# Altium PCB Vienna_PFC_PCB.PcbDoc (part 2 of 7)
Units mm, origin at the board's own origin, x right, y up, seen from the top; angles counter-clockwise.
Board outline 447.04 x 302.51 mm, 6 copper layers (Top Layer, Signal Layer 1, Signal Layer 2, Signal Layer 3, Signal Layer 4, Bottom Layer), stack 1.231 mm thick; 630 components, 255 nets, 1656 pads, 941 vias.
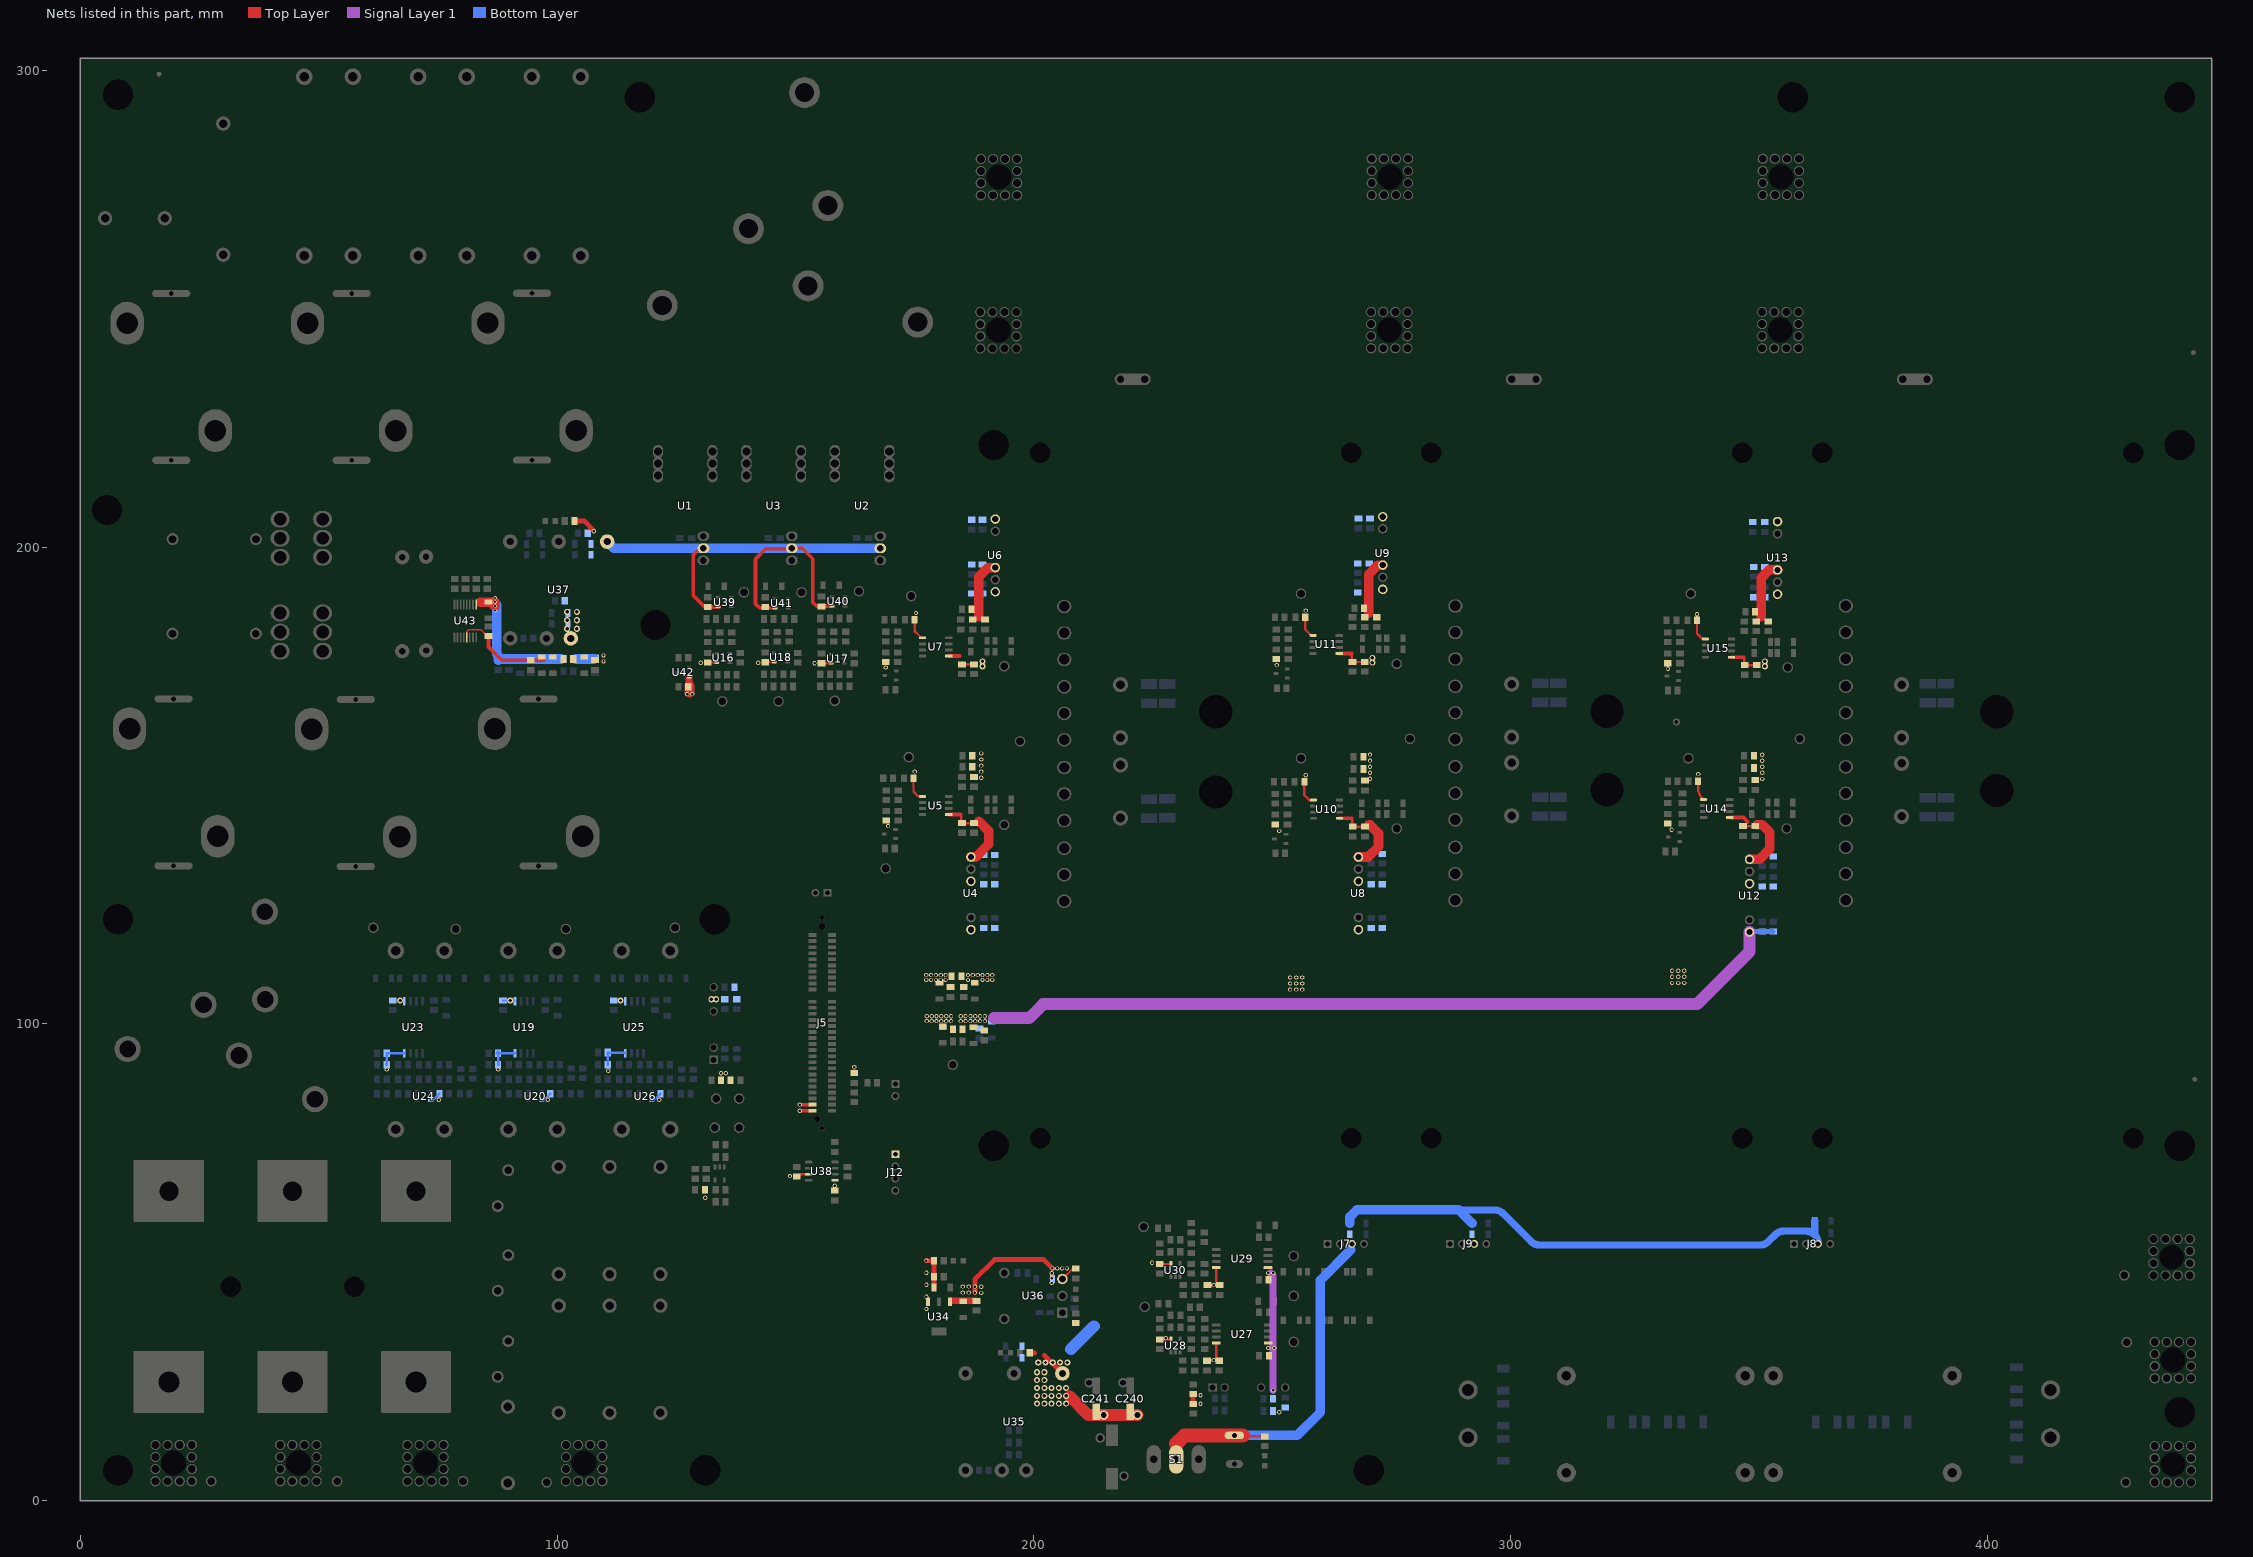
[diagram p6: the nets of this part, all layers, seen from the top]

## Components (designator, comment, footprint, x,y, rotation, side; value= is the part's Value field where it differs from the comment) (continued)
TP_VLI2 "5010" Keystone5010 78.74,119.888 r90 top
TP_VLI3 "5127" Keystone5127 124.714,120.142 r90 top value=Blue
TP_VLM "5012" Keystone5012 61.468,120.142 r90 top
TP_VNM "5011" Keystone5011 254.508,51.308 r90 top
TP_VPM "5010" Keystone5010 254.508,33.274 r90 top
TVS1 "B72214S2271K101" B72214S2271K101 88.646,65.532 r90 top
TVS2 "B72214S2271K101" B72214S2271K101 88.646,47.752 r90 top
TVS3 "B72214S2271K101" B72214S2271K101 88.646,29.718 r90 top
U1 "LAH 100-P" "LAH 100-P" 121.158,220.066 r270 top
U2 "LAH 100-P" "LAH 100-P" 158.242,220.066 r270 top
U3 "LAH 100-P" "LAH 100-P" 139.7,220.066 r270 top
U4 "R12P22005D" R12P22005D 189.484,127.254 r90 top
U5 "UCC5390S" UCC5390S 179.324,145.923 r0 top
U6 "R12P22005D" R12P22005D 189.23,198.374 r270 top
U7 "UCC5390S" UCC5390S 179.324,179.197 r0 top
U8 "R12P22005D" R12P22005D 270.764,127.254 r90 top
U9 "R12P22005D" R12P22005D 270.51,198.882 r270 top
U10 "UCC5390S" UCC5390S 261.317,145.161 r0 top
U11 "UCC5390S" UCC5390S 261.239,179.705 r0 top
U12 "R12P22005D" R12P22005D 352.806,126.746 r90 top
U13 "R12P22005D" R12P22005D 353.314,197.866 r270 top
U14 "UCC5390S" UCC5390S 343.154,145.288 r0 top
U15 "UCC5390S" UCC5390S 343.524,178.943 r0 top
U16 "MCP6021T-E/OT" OPA320 134.874,176.784 r180 top
U17 "MCP6021T-E/OT" OPA320 158.855,176.591 r180 top
U18 "MCP6021T-E/OT" OPA320 146.939,176.862 r180 top
U19 "AMC1301DWVR" AMC1301 93.091,99.314 r270 bottom
U20 "MCP6021T-E/OT" OPA320 95.377,84.836 r0 bottom
U21 "REF2033" REF2033 135.052,69.952 r180 top
U22 "DCH010505SN7" DCH010505SN7 132.842,100.076 r90 top
U23 "AMC1301DWVR" AMC1301 69.85,99.314 r270 bottom
U24 "MCP6021T-E/OT" OPA320 72.009,84.836 r0 bottom
U25 "AMC1301DWVR" AMC1301 116.205,99.314 r270 bottom
U26 "MCP6021T-E/OT" OPA320 118.491,84.836 r0 bottom
U27 "AMC1301DWVR" AMC1301 243.688,34.927 r180 top
U28 "MCP6021T-E/OT" OPA320 229.718,32.514 r90 top
U29 "AMC1301DWVR" AMC1301 243.662,50.775 r180 top
U30 "MCP6021T-E/OT" OPA320 229.692,48.362 r90 top
U31 "DCH010505SN7" DCH010505SN7 245.11,23.718 r0 top
U34 "MIC39100-3.3WS-TR" TLV1117 180.086,38.608 r270 top
U35 "S24SE12002PDFA" S24SE12002NDFA 198.374,6.35 r90 top
U36 "PTH08080WAH" PTH08080WAH 199.898,42.926 r180 top
U37 "S24DE150R3PDFA" S24SE12002NDFA 102.87,180.848 r90 top
U38 "ATA6561-GAQW-N" SOIC8 152.781,70.993 r0 top value=Value
U39 "MCP6V51T-E/OTCT-ND" OPA192 135.128,188.468 r180 top
U40 "MCP6V51T-E/OTCT-ND" OPA192 159.004,188.595 r180 top
U41 "MCP6V51T-E/OTCT-ND" OPA192 147.088,188.214 r180 top
U42 "REF3033AIDBZR" SOT-23 126.492,173.736 r180 top
U43 "TC78H611FNG" "TSSOP16_small pins" 80.731,184.51 r90 top
W1 "36-3065-ND" "WASHER SHOULDER" 191.581,74.415 r0 top
W2 "36-3065-ND" "WASHER SHOULDER" 7.874,6.35 r0 top
W3 "36-3065-ND" "WASHER SHOULDER" 440.341,18.542 r0 top
W4 "36-3065-ND" "WASHER SHOULDER" 440.341,74.415 r0 top
W5 "36-3065-ND" "WASHER SHOULDER" 191.581,221.415 r0 top locked
W6 "36-3065-ND" "WASHER SHOULDER" 117.348,294.386 r0 top
W7 "36-3065-ND" "WASHER SHOULDER" 133.064,121.92 r0 top
W8 "36-3065-ND" "WASHER SHOULDER" 440.341,221.415 r0 top
W9 "36-3065-ND" "WASHER SHOULDER" 7.874,121.92 r0 top
W10 "36-3065-ND" "WASHER SHOULDER" 5.588,207.772 r0 top
W11 "36-3065-ND" "WASHER SHOULDER" 120.65,183.642 r0 top
W12 "36-3065-ND" "WASHER SHOULDER" 131.064,6.35 r0 top
W13 "36-3065-ND" "WASHER SHOULDER" 7.874,294.894 r0 top
W14 "36-3065-ND" "WASHER SHOULDER" 270.256,6.35 r0 top
W15 "36-3065-ND" "WASHER SHOULDER" 359.156,294.386 r0 top
W16 "36-3065-ND" "WASHER SHOULDER" 440.341,294.386 r0 top
XF1 "Fuse Set" FuseHolde_Set 44.45,44.892 r90 top
XF2 "CG2470L" CG2470L 89.662,11.684 r270 top

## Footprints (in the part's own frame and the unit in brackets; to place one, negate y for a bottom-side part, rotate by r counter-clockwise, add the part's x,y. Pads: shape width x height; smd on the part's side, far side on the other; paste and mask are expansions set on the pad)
0805_HV [mil] "0805 with 30mil clearance between pads"
  rect 50x63 smd: 1(-40,0) 2(40,0)
  silkscreen extent -74,-40 74,40, body extent -43,-29 43,29, height 57
1206_190 [mm] "1206_190"
  rect 1.1x1.6 smd: 1(-1.7,0) 2(1.7,0)
  silkscreen extent -0.9,-1 0.9,1, body extent -1.75,-0.95 1.75,0.95, height 1.9
1812 [mm] "SMD, 2-Leads, Body 4.8x3.4mm"
  rect 2x3.4 smd: 1(-2,0) 2(2,0)
  silkscreen extent -0.8,-1.7 0.8,1.7, body extent -2.4,-1.7 2.4,1.7, height 2.54
2010 [mm] "Chip Capacitor, Body 5.08x2.54mm, IPC Medium Density"
  rect 1.6x2.7 smd: 1(-2.3,0) 2(2.3,0)
  silkscreen extent -3.42,-1.65 3.42,1.65, body extent -2.73,-1.45 2.73,1.45, height 1.66
AGP4233-332ME [mm] "Inductor"
  oval 1.5x8 hole 1 square: 0(-17.5,0) 0(17.5,0)
  oval 9x7 hole 4.5 square: 1(-11.274,-9.25) 2(11.274,9.25)
  silkscreen extent -22,-18.8 22,18.8, body extent -21.6,-18.4 21.6,18.4, height 31.3
AMC1301 [mm] "SOIC, 8-Leads, Body 5.95x7.6mm (max), Pitch 1.27mm"
  rrect17% 1.8x0.6 smd: 1(-5.45,1.905) 2(-5.45,0.635) 3(-5.45,-0.635) 4(-5.45,-1.905) 5(5.45,-1.905) 6(5.45,-0.635) 7(5.45,0.635) 8(5.45,1.905)
  silkscreen extent -6.25,-2.95 2.98,2.95, body extent -5.77,-2.92 5.77,2.93, height 2.67
AW220KE [mm] "Res"
  round 2.5 hole 1.6: 1(-8.75,0) 2(8.75,0)
  silkscreen extent -10.41,-6.6 10.41,6.6, body extent -10.03,-6.49 9.96,6.49, height 5.21
AX10GKE [mm] "Res"
  round 3 hole 1.8: 1(-6.25,0) 2(6.25,0)
  silkscreen extent -7.87,-10.8 7.75,10.8, body extent -7.53,-10.5 7.46,10.5, height 6.2
B72214S2271K101 [mm] "Capacitor"
  round 2.5 hole 1.5: 1(-3.75,1.1) 2(3.75,-1.1)
  silkscreen extent -8.13,-3.05 8.13,3.05, body extent -7.75,-2.1 7.75,2.1, height 18.5
Boost_Inductor [mm] "Boost_Inductor"
  round 2.15 hole 1.65: 1(-45.085,12.319) 1(-45.085,14.859) 1(-45.085,17.399) 1(-45.085,19.939) 1(-42.545,12.319) 1(-42.545,19.939) 1(-40.005,12.319) 1(-40.005,19.939) 1(-37.465,12.319) 1(-37.465,14.859) 1(-37.465,17.399) 1(-37.465,19.939) 2(-45.212,-19.812) 2(-45.212,-17.272) 2(-45.212,-14.732) 2(-45.212,-12.192) 2(-42.672,-19.812) 2(-42.672,-12.192) 2(-40.132,-19.812) 2(-40.132,-12.192) 2(-37.592,-19.812) 2(-37.592,-17.272) 2(-37.592,-14.732) 2(-37.592,-12.192)
  round 3.9 hole 5.2: 1(-41.275,16.129) 2(-41.402,-16.002)
  silkscreen extent -46.91,-22.1 32,22.1, body extent -45.8,-22.1 41,22.1, height 71.62
Bush7460408 [mm] "Power Connecter 12pin"
  round 2.15 hole 1.65: 1(0,-7.62) 1(0,-5.08) 1(0,-2.54) 1(0,0) 1(2.54,-7.62) 1(2.54,0) 1(5.08,-7.62) 1(5.08,0) 1(7.62,-7.62) 1(7.62,-5.08) 1(7.62,-2.54) 1(7.62,0)
  round 3.9 hole 5.2: 1(3.81,-3.81)
  silkscreen extent -1.7,-9.4 9.53,1.78, body extent -0.59,-8.31 8.41,0.69, height 6
CG2470L [mm] "Capacitor"
  round 3 hole 1.8: 1(-8,0) 2(8,0)
  silkscreen extent -9.65,-4.57 9.65,4.57, body extent -2.79,-4.06 3.04,4.06, height 8.5
DCH010505SN7 [mm] "Module, 4-Leads, Body 19.56x7.62mm"
  rect 1.75x1.75 hole 1.25: 1(-7.62,0)
  round 1.75 hole 1.25: 2(-5.08,0) 5(2.54,0) 7(7.62,0)
  silkscreen extent -9.78,-6.35 9.78,2.54, body extent -9.78,-6.35 9.78,1.27, height 10.15
E92X451VSN471MA50 [mm] "Capacitor"
  round 4 hole 2.5: 1(-5,0) 2(5,0)
  silkscreen extent -17.5,-17.5 17.5,17.5, body extent -24.63,-24.62 24.11,24.12, height 50
EW60-1A3-BL12D04,00000 [mm] "Capacitor"
  round 3 hole 1.35: 1(30.6,0.128) 2(25.6,0)
  oval 4x3.5 hole 2.65: 4(0,0) 4(0,4) 4(0,8) 5(8.9,0) 5(8.9,4) 5(8.9,8)
  silkscreen extent -3.05,-2.92 34.8,15.37, body extent -2.51,-2.38 34.29,14.82, height 30.4
EZP-E50556MTA [mm] "Capacitor"
  round 4 hole 2: 1(-18.75,-10.15) 1(-18.75,10.15) 2(18.75,-10.15) 2(18.75,10.15)
  silkscreen extent -21.34,-15.49 21.34,15.49, body extent -20.77,-15.01 20.73,14.99, height 51.5
"Fan Connector" [mm]
  round 1.65 hole 1.016: 1(3.81,0) 2(1.27,0) 3(-1.27,0)
  rrect6% 1.65x1.65 hole 1.016: 4(-3.81,0)
  silkscreen extent -5.46,-2.54 5.08,3.43, body extent -5.08,-1.27 5.08,3.05, height 8.38
Fiducial10-20 [mm]
  round 1 smd mask+0.5: 1(0,0)
  Top Layer keep-out circle w1.178: c0,0 r0.5
FuseHolde_Set [mm]
  round 0 hole 4.3: 0(0,12.954) 0(0,-12.945)
  rect 13x14.7 hole 4.4: 1(-20,25.908) 3(-20,0) 5(-20,-25.908)
  rect 13x14.7 hole 4: 2(20,25.908) 4(20,0) 6(20,-25.908)
  silkscreen extent -29.21,-39.37 29.21,39.37, body extent -25.65,-32.91 25.6,32.91, height 19
HDR_F_1.27_2X30_V_SMD_MECF-30-01-L-DV-WT [mm]
  round 1.1 hole 1 unplated mask+0.075: 0(-22.075,0) 0(22.125,0)
  round 1.5 hole 1.4 unplated mask+0.075: 0(-20.2,0) 0(20.175,-1)
  rect 0.8x1.7 smd mask+0.075: 1(-18.41,-2.01) 2(-18.41,2.05) 3(-17.14,-2.01) 4(-17.14,2.05) 5(-15.87,-2.01) 6(-15.87,2.05) 7(-14.6,-2.01) 8(-14.6,2.05) 9(-13.33,-2.01) 10(-13.33,2.05) 11(-12.06,-2.01) 12(-12.06,2.05) 13(-10.79,-2.01) 14(-10.79,2.05) 15(-9.52,-2.01) 16(-9.52,2.05) 17(-8.25,-2.01) 18(-8.25,2.05) 19(-6.98,-2.01) 20(-6.98,2.05) 23(-4.44,-2.01) 24(-4.44,2.05) 25(-3.17,-2.01) 26(-3.17,2.05) 27(-1.9,-2.01) 28(-1.9,2.05) 29(-0.63,-2.01) 30(-0.63,2.05) 31(0.64,-2.01) 32(0.64,2.05) 33(1.91,-2.01) 34(1.91,2.05) 35(3.18,-2.01) 36(3.18,2.05) 37(4.45,-2.01) 38(4.45,2.05) 39(5.72,-2.01) 40(5.72,2.05) 41(6.99,-2.01) 42(6.99,2.05) 43(8.26,-2.01) 44(8.26,2.05) 45(9.53,-2.01) 46(9.53,2.05) 47(10.8,-2.01) 48(10.8,2.05) 49(12.07,-2.01) 50(12.07,2.05) 51(13.34,-2.01) 52(13.34,2.05) 53(14.61,-2.01) 54(14.61,2.05) 55(15.88,-2.01) 56(15.88,2.05) 57(17.15,-2.01) 58(17.15,2.05) 59(18.42,-2.01) 60(18.42,2.05)
  silkscreen extent -23.35,-4.75 23.43,3.18, body extent -23.1,-2.8 23.18,2.8, height 8.76
"Hole-Dia 4.3mm" [mm] "Hole-Dia 4.3mm"
  round 0 hole 4.3: 0(0,0)
  Keep-Out Layer circle w0.1: c0,0 r2.15
  silkscreen extent -4,-4 4,4
IEC_HighVoltage_Small [mm]
  silkscreen extent -2.72,-2.24 2.72,2.47
IEC_HotSurface_Small [mm]
  silkscreen extent -2.72,-2.36 2.72,2.35
Keystone5010 [mil] "Keystone Multipurpose loops"
  round 87 hole 63: 1(0,0)
  silkscreen extent -70,-70 70,70, body extent -63,-63 63,62, height 319
Keystone5011 [mil] "Keystone Multipurpose loops"
  round 87 hole 63: 1(0,0)
  silkscreen extent -70,-70 70,70, body extent -63,-63 63,62, height 319
Keystone5012 [mil] "Keystone Multipurpose loops"
  round 87 hole 63: 1(0,0)
  silkscreen extent -70,-70 70,70, body extent -63,-63 63,62, height 319
Keystone5127 [mil] "Keystone Multipurpose loops"
  round 87 hole 63: 1(0,0)
  silkscreen extent -70,-70 70,70, body extent -63,-63 63,62, height 319
"LAH 100-P" [mm] "Inductor"
  oval 2.8x2.2 hole 1.7 slot 2.2 at 0 deg: 1(5.08,0) 2(2.54,0) 3(0,0) 4(5.08,11.43) 5(2.54,11.43) 6(0,11.43)
  oval 2x2.5 hole 1.4: 7(22.86,9.525) 8(20.32,9.525) 9(17.78,9.525)
  silkscreen extent -8.05,-2.03 25.91,13.46, body extent -7.76,-1.73 25.54,13.21, height 21.05
M2011SS1W01 [mm] "Capacitor"
  oval 6x3 hole 1.6 square: 1(0,-4.7) 2(0,0) 3(0,4.7)
  silkscreen extent -6.35,-6.86 6.35,6.86, body extent -6.02,-6.51 5.97,6.5, height 28.88
MKP1847H55035JP4 [mm] "Capacitor"
  round 3.5 hole 2: 1(-18.75,-5.1) 1(-18.75,5.1) 2(18.75,-5.1) 2(18.75,5.1)
  silkscreen extent -21.59,-11.43 21.59,11.43, body extent -21.35,-11.1 21.35,11.1, height 39
OPA192 [mm] "SOT23, 5-Leads, Body 2.9x1.6mm, Pitch 0.95mm, Lead Span 2.8mm, IPC Medium Density"
  rrect17% 1x0.6 smd: 1(-1.375,0.95) 2(-1.375,0) 3(-1.375,-0.95) 4(1.375,-0.95) 5(1.375,0.95)
  silkscreen extent -1.63,-1.55 0.38,1.55, body extent -1.42,-1.46 1.42,1.46, height 1.09
OPA320 [mm] "SOT23, 5-Leads, Body 2.9x1.6mm, Pitch 0.95mm, Lead Span 2.8mm, IPC Medium Density"
  rrect17% 1x0.6 smd: 1(-1.375,0.95) 2(-1.375,0) 3(-1.375,-0.95) 4(1.375,-0.95) 5(1.375,0.95)
  silkscreen extent -1.63,-1.55 0.38,1.55, body extent -1.42,-1.46 1.42,1.46, height 1.09
PJ-037AH [mm] "Power Jack, 2mm, R/A, TH"
  oval 4.1x1.6 hole 1 slot 3.5 at 0 deg: 1(0,3)
  oval 3.6x1.6 hole 1 slot 3 at 0 deg: 2(0,-3)
  silkscreen extent -4.5,-10.3 4.5,3.8, body extent -4.5,-10.7 4.5,3.8, height 11
PTH08080WAH [mm]
  rect 2.2x2.2 hole 1.4: 1(-6.096,3.556)
  round 2.2 hole 1.4: 2(-6.096,0) 3(-6.096,-3.556) 4(6.096,-4.826) 5(6.096,4.826)
  silkscreen extent -8.53,-6.35 7.62,6.35, body extent -7.62,-6.35 7.62,6.35, height 8.18
"Quick Connect-4.75mm" [mm] "Quick Connect-4.75mm"
  round 2.5 hole 1.5: 1(-2.54,0) 1(2.54,0)
  rrect50% 6x2.5 smd: 1(0,0)
  silkscreen extent -4.32,-1.78 4.32,1.78, body extent -3.81,-1.27 3.81,1.27, height 9
R12P22005D [mm]
  round 2 hole 1.3: 1(-7.498,2.68) 2(-4.958,2.68) 5(2.662,2.68) 6(5.202,2.68) 7(7.742,2.68)
  silkscreen extent -9.91,-5.33 10.16,5.59, body extent -9.4,-4.83 9.65,5.08, height 12.5
R413N310040M1M [mm] "Capacitor"
  round 3 hole 1.8: 1(-11.25,0) 2(11.25,0)
  silkscreen extent -13.97,-4.83 13.97,4.83, body extent -13.46,-4.35 13.34,4.35, height 17.1
R413R34700000M [mm] "Capacitor"
  round 3 hole 1.8: 1(-13.75,0) 2(13.75,0)
  silkscreen extent -16.76,-9.65 16.51,9.65, body extent -16.13,-9.1 16.17,9.1, height 33.1
REF2033 [mm]
  rect 0.6x1.1 smd: 1(0,0) 2(0.95,0) 3(1.9,0) 4(1.9,2.7) 5(0,2.7)
  silkscreen extent -1.52,0.13 3.05,1.91, body extent -0.51,0 2.41,2.84, height 1.09
S24SE12002NDFA [mil]
  round 120 hole 60: 1(0,0) 2(0,200) 3(0,500) 4(800,500) 5(800,100) 6(800,-300)
  silkscreen extent -120,-420 920,620, body extent -120,-420 920,620, height 402
Samtec_HTSW-102-07-G-S [mm] "Samtec 100mil, 1x2, 230 mil above insulator"
  rrect6% 1.65x1.65 hole 1.016: 1(-1.27,0)
  round 1.65 hole 1.016: 2(1.27,0)
  silkscreen extent -3.3,-1.27 2.54,1.27, body extent -2.54,-1.27 2.54,1.27, height 8.38
SM_RADIAL_6.3BMM [mm] "Nichicon 6.3x7.7"
  round 2 hole 1.2: 1(-3.4,-1.524) 2(3.4,1.524)
  rect 3.5x1.6 smd: 1(-2.7,0) 2(2.7,0)
  silkscreen extent -3.4,-3.4 3.4,3.4, body extent -3.4,-3.4 3.4,3.4, height 8
SM_RADIAL_10BMM [mm] "Nichicon 10x10.5"
  rect 4.5x2.5 smd: 1(-4.572,0) 2(4.572,0)
  round 2 hole 1.2: 1(-4,-2.5) 2(4,2.5)
  silkscreen extent -5.33,-5.33 5.33,5.33, body extent -5.39,-5.33 5.39,5.33, height 10.5
SOIC8 [mm]
  oval 1.52x0.6 smd: 1(0,0)
  rect 1.52x0.6 smd: 2(0,-1.27) 3(0,-2.54) 4(0,-3.81) 5(5.48,-3.81) 6(5.48,-2.54) 7(5.48,-1.27) 8(5.48,0)
  silkscreen extent -1.02,-4.95 6.53,1.12, body extent 1.27,-4.83 4.32,1.02, height 1.7
SOT-23 [mm] "SOT23, 3-Leads, Body 2.9x1.3mm, Pitch 0.95mm, Lead Span 2.5mm, IPC Medium Density"
  rrect50% 1x0.6 smd: 1(-1.2,0.95) 2(-1.2,-0.95) 3(1.2,0)
  silkscreen extent -1.62,-1.5 0.7,1.5, body extent -1.16,-1.45 1.21,1.45, height 1
T60405-S6123-X140 [mm] "Common mode choke"
  round 5.5 hole 3.5: 1(-3.17,-6.797) 2(-22.699,6.082) 3(-4.302,6.144) 4(16.617,16.617) 5(7.471,0.654) 6(6.082,-22.699)
  silkscreen extent -25.5,-25.5 25.5,25.5, body extent -25.91,-26.16 26.09,25.83, height 32
T60405-S6123-X240 [mm] "Common mode choke"
  round 6.5 hole 4: 1(-26.847,15.5) 2(-6.428,-7.66) 3(0,-31) 4(9.848,-1.736) 5(26.847,15.5) 6(-3.42,9.397)
  silkscreen extent -36,-36 36,36, body extent -34.97,-34.97 34.92,34.9, height 36
TLV1117 [mm] "SOT223/SC73, 4-Leads, Body 6.5x3.5mm, Pitch 2.3mm, Lead Span 7mm, IPC Medium Density"
  rrect11% 1.75x0.9 smd: 1(-3.125,2.3) 2(-3.125,0) 3(-3.125,-2.3)
  rrect6% 1.75x3.2 smd: 4(3.125,0)
  silkscreen extent -3.02,-3.35 1.4,3.48, body extent -3.48,-3.25 3.48,3.25, height 1.68
TO-247 [mm]
  oval 2.8x3 hole 2.2: 1(0,0) 2(5.563,0) 3(11.125,0)
  silkscreen extent -2.54,-2.54 13.46,2.54, body extent -2.16,-2.67 13.08,1.91, height 20.33
TO-247-ress [mm]
  round 0 hole 7: 0(5.45,20)
  round 3.2 hole 1.8 slot 2.5 at 0 deg: 1(0,0) 2(11.125,0)
  silkscreen extent -2.44,-3.39 13.41,25.5, body extent -2.49,-0.5 13.41,25.4, height 5.26
"TSSOP16_small pins" [mm] "SOP, 16-Leads, Body 6.2x5.3mm, Pitch 0.65mm, IPC Medium Density"
  oval 2.1x0.35 smd: 1(-3.45,2.275) 2(-3.45,1.625) 3(-3.45,0.975) 4(-3.45,0.325) 5(-3.45,-0.325) 6(-3.45,-0.975) 7(-3.45,-1.625) 8(-3.45,-2.275) 9(3.45,-2.275) 10(3.45,-1.625) 11(3.45,-0.975) 12(3.45,-0.325) 13(3.45,0.325) 14(3.45,0.975) 15(3.45,1.625) 16(3.45,2.275)
  silkscreen extent -3.57,-3.25 2,3.25, body extent -2.7,-3.25 2.7,3.25, height 2
UCC5390S [mm] "SOIC, 8-Leads, Body 5.95x7.6mm (max), Pitch 1.27mm"
  oval 1.52x0.6 smd: 1(-2.667,1.778)
  rect 1.52x0.6 smd: 2(-2.667,0.508) 3(-2.667,-0.762) 4(-2.667,-2.032) 5(2.813,-2.032) 6(2.813,-0.762) 7(2.813,0.508) 8(2.813,1.778)
  silkscreen extent -3.68,-3.17 3.86,2.9, body extent -1.4,-3.05 1.65,2.79, height 1.7
"WASHER SHOULDER" [mm] "WASHER SHOULDER"
  round 4.35 hole 6.35: 0(0,0)
  Keep-Out Layer circle w0.1: c0,0 r3.175
  silkscreen extent -5,-5 5,5, body extent -4.5,-4.5 4.5,4.5, height 3.58
WL-SMCW_Green_0805 [mm] "SMD, 2-Leads, Body 2x1.25mm"
  rect 1.1x1.2 smd: 1(-1.05,0) 2(1.05,0)
  silkscreen extent -2.4,-1.1 1.5,1.1, body extent -1,-0.62 1,0.63, height 0.7

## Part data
C1 C2 C4 C6 C21 C23 C25 C26 C27 C30 C31 C35 C37 C39 C41 C43 C45 C47 C55 C56 C57 C59 C61 C64 C65 C66 C67 C69 C72 C75 C77 C79 C83 C85 C87 C90 C91 C92 C93 C95 C98 C101 C103 C105 C109 C111 C113 C116 C118 C119 C121 C122 C124 C128 C129 C131 C133 C134 C137 C139 C142 C144 C146 C147 C149 C152 C154 C156 C157 C159 C163 C165 C166 C168 C173 C196 C197 C198 C208 C213 C217 C218 C222 C225 C229 C231 C239 C243 C245 C246 C248 C249 C251 C252 C253 C257 C260 C261: "CAP, CERM, 0.1 µF, 50 V, +/- 5%, X7R, 0805", Cap_Case=0805, Manufacturer=Kemet, TempCo=X7R, Tolerance_%=5, ValueDisplayed=0.1µF
C3 C5 C7 C28 C29 C32 C38 C42 C44 C60 C63 C68 C70 C71 C76 C86 C89 C94 C96 C97 C102 C117 C123 C127 C132 C145 C155 C164 C206 C207 C220 C227 C238: "CAP, CERM, 4.7 µF, 50 V, +/- 10%, X5R, 0805", Cap_Case=0805, Manufacturer=TDK, TempCo=X5R, Tolerance_%=10, Value1=Unknown, Value2=50V, ValueDisplayed=4.7µF
C8 C9 C10 C11 C12 C13: "CAP FILM 0.1UF 20% 1KVDC RADIAL", Manufacturer=KEMET, Supplier Part Number 1=399-12673-ND
C14 C15 C16 C17 C18 C19: "CAP FILM 5UF 5% 700VDC RAD 4LDS", Manufacturer="Vishay BC Components", Supplier Part Number 1=BC3335-ND
C20: "CAP FILM 0.47UF 20% 1KVDC RADIAL", Manufacturer=KEMET, Supplier Part Number 1=399-13444-ND
C22 C24 C46 C48 C58 C62 C78 C80 C84 C88 C104 C106 C135 C136 C171 C172 C242: "CAP, CERM, 1 µF, 50 V, +/- 5%, X7R, 0805", Cap_Case=0805, Manufacturer=Kemet, TempCo=X7R, Tolerance_%=10, ValueDisplayed=1µF
C33 C40 C49 C50 C73 C74 C81 C82 C99 C100 C107 C108: "CAP, CERM, 100 pF, 50 V, +/- 5%, X7R, 0805", Cap_Case=0805, Manufacturer=Kemet, TempCo=X7R, Tolerance_%=5, ValueDisplayed=100pF
C34 C36 C51 C52 C53 C54 C190 C191 C194 C195 C211 C212 C215 C216 C221 C228 C232 C233 C234 C235 C236 C237 C256 C259 C262: "CAP, CERM, 10 µF, 25 V, +/- 10%, X7R, 1206_190", Cap_Case=1206, Manufacturer=Kemet, TempCo=X7R, Tolerance_%=10, Value1=Unknown, Value2=25V, ValueDisplayed=10µF
C110 C112 C114 C115 C120 C125 C126 C130 C138 C140 C141 C143 C148 C150 C151 C153 C158 C160 C161 C162 C167 C169 C170: "CAP, CERM, 180 pF, 50 V, +/- 5%, X7R, 0805", Cap_Case=0805, Manufacturer=Kemet, TempCo=X7R, Tolerance_%=5, ValueDisplayed=180pF
C174 C175 C178 C179 C180 C181 C182 C183 C184 C185 C188 C189: "CAP, CERM, 0.1 µF, 630V, +/- 10%, X7R, 1206", Value1=Unknown, Value2=630V, ValueDisplayed=0.1µF
C176 C186: "Aluminum Electrolytic Capacitors - Snap In 450V 470uF 20% Long Life", Manufacturer="United Chemi-Con (UCC)"
C177 C187: "CAP FILM 55UF 10% 500VDC RAD 4LD", Manufacturer="Panasonic Electronic Components", Supplier Part Number 1=P15871-ND
C192 C193 C209 C210 C214 C219 C223 C224 C226 C258: "CAP, CERM, 33 µF, 25 V, +/- 20%, X5R, 1206", Cap_Case=1206, Manufacturer=TDK, TempCo=X5R, Tolerance_%=20, Value1=Unknown, Value2=25V, ValueDisplayed=33µF
C230: "CAP, Polymer Hybrid, 100 µF, 50 V, +/- 20%, 30 ohm, 6.3x7.7 SMD", Manufacturer=Panasonic, Tolerance_%=20, Value1="30 ohm", Value2=50V, ValueDisplayed=100µF
C240 C241: "CAP, Polymer Hybrid, 100 µF, 25 V, +/- 20%, 30 ohm, 6.3x7.7 SMD", Manufacturer=Panasonic, Tolerance_%=20, Value1="30 ohm", Value2=25V, ValueDisplayed=100µF
C244 C247 C250: "CAP, CERM, 10 nF, 50 V, +/- 5%, X7R, 0805", Cap_Case=0805, Manufacturer=Kemet, PartNumber=C0805C104J5RACTU, TempCo=X7R, Tolerance_%=5, ValueDisplayed=0.1µF
"CAUTION! High Voltage1" "CAUTION! High Voltage2" "CAUTION! High Voltage Input1" "CAUTION! High Voltage Output1": library part IEC_HighVoltage, "IEC 61010-1 High Voltage Warning"
"CAUTION! HOT SURFACE!1" "CAUTION! HOT SURFACE!!1": library part IEC_HotSurface, "IEC 61010-1 Hot Surface Warning"
D1 D2 D3 D4 D5 D6: "DIODE SCHOTTKY 1.2KV 30A TO247", Manufacturer="Microsemi Corporation", Supplier Part Number 1=MSC030SDA120B-ND
D9 D10 D11 D12 D13: "LED, Bright Green, SMD", Color="Bright Green", Manufacturer="Wurth Elektronik", Power_TotalModule=0.072, Value1=0.072W, Value2=2V
FID1 FID2 FID3 FID4 FID5 FID6: "Fiducial mark.  There is nothing to buy or mount.", Manufacturer=N/A
Hole1 Hole2 Hole3 Hole4 Hole5 Hole6 Hole7 Hole8 Hole9 Hole10 Hole11 Hole12: library part Hole, "Hole  Dia 4.3mm"
J1 J4: "Header, 100mil, 2x1, Gold, TH", Manufacturer=Samtec, Supplier Part Number 1=SAM8736-ND
J5: "Get it already"
J6: "Power Jack, 2mm, R/A, TH", Color=Black, Manufacturer="CUI Inc.", Supplier Part Number 1=CP-037AH-ND
J7 J8 J9 J12: "4 Positions Header Connector 0.100\" (2.54mm) Through Hole Tin", Manufacturer="TE Connectivity AMP Connectors", Supplier Part Number 1=A1922-ND
L1 L2 L3 L4 L5 L6 L7 L8 L9 L10: "Ferrite Bead, 30 ohm @ 100 MHz, 6 A, 0805", Manufacturer=TDK, Supplier Part Number 1=445-1566-1-ND, Value1="0.01 ohm", Value2=6A
Lboost1 Lboost2 Lboost3: "Boost_Inductor, Handmake"
Lcm1: "Common Mode Chokes / Filters 580 uH 40A horiz. 2.5mH", Manufacturer=Vacuumschmelze
Lcm2: "Common Mode Chokes / Filters CM Choke 3 phase 40A horiz. 1.5mH", Manufacturer=Vacuumschmelze
Ldm1 Ldm2 Ldm3 Ldm4 Ldm5 Ldm6: "FIXED IND 3.3UH 34A  TH, Coilcraft", Manufacturer=Coilcraft
P1 P2 P3 P4 P5 P6 P7: "TERM PWR ELEMENT M5 12 PIN PCB", Manufacturer="Wurth Electronics Inc.", Supplier Part Number 1=732-3208-ND
P8 P9 P10: "0.187\" (4.75mm) Quick Connect Male Solder"
Q1 Q2 Q3 Q4 Q5 Q6: "MOSFET, N-CH, 60 V, 115 MA, SOT-23", Alternate Manufacturer=None, Manufacturer="Fairchild Semiconductor", Supplier Part Number 1=2N7002NCT-ND, Value1="? ohm", Value2="? nC"
Q7 Q8 Q9 Q10 Q11 Q12 Q13 Q14 Q15 Q16 Q17 Q18: library part MSC015SMA070B, "GEN2 SIC MOSFET 700V 15MOHM TO-247-3", Manufacturer="Microsemi Corporation", Supplier Part Number 1=MSC040SMA120B-ND
R2: library part CRCW08054K70FKEA, "RES, 4.7K, 1%, 0.125 W, 0805", Manufacturer=Vishay-Dale, Power_W=0.125, TempCo="100 ppm/C", Tolerance_%=1, Value1=1%, Value2=0.125W, Value_Code=4.7k
R3: library part CRCW08054K70FKEA, "RES SMD 68.1 OHM 1% 1/8W 0805", Manufacturer=Vishay-Dale, PartNumber=CRCW080568R1FKEA, Power_W=0.125, TempCo="100 ppm/C", Tolerance_%=1, Value1=1%, Value2=0.125W, Value_Code=68.1
R4: "RES 1 OHM 3.5W 10% RADIAL", Manufacturer=Ohmite, Supplier Part Number 1=AX10GKE-ND
R5 R6 R8 R21 R22 R23 R25 R27 R38 R39 R41 R43 R162: "RES, 0, 5%, 0.125 W, 0805", Manufacturer=Vishay-Dale, Power_W=0.125, TempCo="200 ppm/C", Tolerance_%=5, Value1=5%, Value2=0.125W, Value_Code=0
R7 R9 R19 R20 R24 R26 R36 R37 R40 R42 R52 R53: "RES, 100, 1%, 0.125 W, 0805", Manufacturer=Vishay-Dale, Power_W=0.125, TempCo="100 ppm/C", Tolerance_%=1, Value1=1%, Value2=0.125W, Value_Code=100R, ValueDisplayed=100
R10 R168 R170: "RES, 0, 5%, 0.125 W, 0805", Manufacturer=Vishay-Dale, Power_W=0.125, TempCo="200 ppm/C", Tolerance_%=5, Value1=5%, Value2=DNF, Value_Code=0
R11 R12 R28 R29 R44 R45: library part CRCW12062R20FKEAHP, "RES, 2.2, 1%, 0.75 W, 1206", Manufacturer=Vishay-Dale, Power_W=0.75, TempCo="100 ppm/C", Tolerance_%=1, Value1=1%, Value2=0.75W, Value_Code=2R2, ValueDisplayed=2.2
R13 R15 R30 R32 R46 R48 R138 R139 R140 R141 R142 R143 R144 R145 R150 R151 R154 R155: library part CRCW12064R70FKEAHP, "RES, 4.7, 1%, 0.75 W, 1206", Manufacturer=Vishay-Dale, Power_W=0.75, TempCo="100 ppm/C", Tolerance_%=1, Value1=1%, Value2=0.75W, Value_Code=4R7, ValueDisplayed=4.7
R14 R16 R31 R33 R47 R49: library part TNPW08052K20BEEA, "RES 2.2K OHM 0.1% 1/5W 0805", Manufacturer=Vishay-Dale, Power_W=0.125, TempCo="100 ppm/C", Tolerance_%=1, Value1=1%, Value2=0.125W, Value_Code=100R, ValueDisplayed=2.2k
R17 R18 R34 R35 R50 R51: "RES, 680, 1%, 0.125 W, 0805", Manufacturer=Vishay-Dale, Power_W=0.125, TempCo="100 ppm/C", Tolerance_%=1, Value1=1%, Value2=0.125W, Value_Code=680R, ValueDisplayed=680
R54 R60 R61 R66 R172 R175: "RES 2.2K OHM 0.1% 1/5W 0805", Manufacturer=Vishay, Power_W=0.2W, TempCo=25ppm/C, Tolerance_%=0.1
R55: "RES, 120, 1%, 0.125 W, 0805", Manufacturer=Vishay-Dale, Power_W=0.125, TempCo="100 ppm/C", Tolerance_%=1, Value1=1%, Value2=0.125W, Value_Code=120R, ValueDisplayed=120
R56 R62 R68 R79 R91 R103 R115 R127: "RES, 68.1, 1%, 0.125 W, 0805", Manufacturer=Vishay-Dale, Power_W=0.125, TempCo="100 ppm/C", Tolerance_%=1, Value1=1%, Value2=0.125W, Value_Code=68R1, ValueDisplayed=68.1
R57 R63 R69: "RES 40.2K OHM 0.1% 1/5W 0805", Manufacturer=Vishay, Power_W=0.2W, TempCo=25ppm/C, Tolerance_%=0.1
R58 R64: "RES 1K OHM 0.1% 1/5W 0805", Manufacturer=Vishay, Power_W=0.2W, TempCo=25ppm/C, Tolerance_%=0.1
R59 R65 R71: "RES 10K OHM 0.1% 1/5W 0805", Manufacturer=Vishay, Power_W=0.2W, TempCo=25ppm/C, Tolerance_%=0.1
R67 R173 R176: "RES 160R OHM 0.1% 1/5W 0805", Manufacturer=Vishay, Power_W=0.2W, TempCo=25ppm/C, Tolerance_%=0.1
R70: library part TNPW08051K00BEEA, "RES 1K OHM 0.1% 1/5W 0805", Manufacturer=Vishay, Power_W=0.2W, TempCo=25ppm/C, Tolerance_%=0.1
R72 R73 R75 R84 R85 R87 R96 R97 R99 R108 R109 R111 R120 R121 R123: "RES, 1 M, 0.1%, 0.25 W, 15 PPM / C, AEC-Q200", Manufacturer=Vishay, Power_W=0.25W, TempCo=15ppm/C, Tolerance_%=0.1
R74 R83 R86 R95 R98 R107 R110 R119 R122 R131: "RES, 7.5K, 1%, 0.125 W, 0805", Manufacturer=Vishay-Dale, Power_W=0.125, TempCo="100 ppm/C", Tolerance_%=1, Value1=1%, Value2=0.125W, Value_Code=7.5k
R76 R77 R80 R81 R88 R89 R92 R93 R100 R101 R104 R105 R112 R113 R116 R117 R124 R125 R128 R129: "RES, 4.7K, 1%, 0.125 W, 0805", Manufacturer=Vishay-Dale, Power_W=0.125, TempCo="100 ppm/C", Tolerance_%=1, Value1=1%, Value2=0.125W, Value_Code=4.7k
R78 R82 R90 R94 R102 R106: "RES, 2 k,  0.1%, 0.25 W, 25 PPM / C, AEC-Q200", Manufacturer=Vishay, Power_W=0.25W, TempCo=25ppm/C, Tolerance_%=0.1
R114 R118 R126 R130: "RES, 2.74 k,  0.1%, 0.25 W, 25 PPM / C, AEC-Q200", Manufacturer=Vishay, Power_W=0.25W, TempCo=25ppm/C, Tolerance_%=0.1
R132 R133 R134 R135 R136 R137 R146 R147 R148 R149 R152 R153: "RES, 510 k, 5%, 0.75 W, AEC-Q200 Grade 0, 2010", Manufacturer=Vishay-Dale, Power_W=0.75, Supplier Part Number 1=541-510KWCT-ND, TempCo="200 ppm/C", Tolerance_%=5, Value1=5%, Value2=0.75W, Value_Code=510k
R163 R164: "RES, 4.7K, 1%, 0.125 W, 0805", Manufacturer=Vishay-Dale, Power_W=0.125, TempCo="100 ppm/C", Tolerance_%=1, Value1=1%, Value2=0.125W, Value_Code=4.7k, ValueDisplayed=2k
R165: "RES, 2K, 1%, 0.125 W, 0805", Manufacturer=Vishay-Dale, Power_W=0.125, TempCo="100 ppm/C", Tolerance_%=1, Value1=1%, Value2=0.125W, Value_Code=2k, ValueDisplayed=1k
R166: "RES, 1 k, 1%, 0.125 W, 0805", Manufacturer=Vishay-Dale, Power_W=0.125, TempCo="100 ppm/C", Tolerance_%=1, Value1=1%, Value2=0.125W, Value_Code=1kR, ValueDisplayed=1k
R167: "RES, 348, 1%, 0.125 W, 0805", Manufacturer=Vishay-Dale, Power_W=0.125, TempCo="100 ppm/C", Tolerance_%=1, Value1=1%, Value2=0.125W, Value_Code=348R, ValueDisplayed=348
R169: "RES, 5K, 1%, 0.125 W, 0805", Manufacturer=Vishay-Dale, Power_W=0.125, TempCo="100 ppm/C", Tolerance_%=1, Value1=1%, Value2=0.125W, Value_Code=5k
R171 R174 R177: "RES, 49.9  0.1%, 0.4 W, 25 PPM / C, AEC-Q200", Manufacturer=Vishay, Power_W=0.4W, TempCo=25ppm/C, Tolerance_%=0.1
R178: "RES, 10K, 1%, 0.125 W, 0805", Manufacturer=Vishay-Dale, Power_W=0.125, TempCo="100 ppm/C", Tolerance_%=1, Value1=1%, Value2=0.125W, Value_Code=10k
R180 R181 R182 R183: "RES, 4.99 1%, 0.125 W, 0805", Manufacturer=Vishay-Dale, Power_W=0.125, TempCo="100 ppm/C", Tolerance_%=1, Value1=1%, Value2=0.125W, Value_Code=4R99, ValueDisplayed=4.99
Rsurge1 Rsurge2: "RES 22 OHM 2.5W 10% RADIAL", Manufacturer=Ohmite, Supplier Part Number 1=AW220KE-ND
SW1 SW2: library part EW60-1A3-BL12D04, "RELAY GEN PURPOSE SPST 60A 12V", Manufacturer="TE Connectivity Potter & Brumfield Relays", Supplier Part Number 1=PB2134-ND
TP_BUSM TP_G2 TP_G4 TP_G6 TP_GND TP_GS2 TP_GS4 TP_GS6 TP_N1 TP_PE1 TP_VLM: "Test Point, Multipurpose, White, TH", Color=White, Manufacturer=Keystone, Supplier Part Number 1=36-5012-ND
TP_DGND1 TP_GND1 TP_GND2 TP_GND3 TP_IIn1 TP_IL1 TP_V1 TP_VBUSMN_Fdbk1 TP_VL1 TP_VL8 TP_VLI1 TP_VNM: "Test Point, Multipurpose, Black, TH", Color=Black, Manufacturer=Keystone, Supplier Part Number 1=36-5011-ND
TP_EN1 TP_IIn3 TP_IL3 TP_V3 TP_VL3 TP_VLI3: "Test Point, Multipurpose, Blue, TH", Color=Blue, Manufacturer=Keystone, Supplier Part Number 1=36-5127-ND
TP_G1 TP_G3 TP_G5 TP_GS1 TP_GS3 TP_GS5 TP_IIn2 TP_IL2 TP_V2 TP_VBUSPM_Fdbk1 TP_VL2 TP_VL7 TP_VLI2 TP_VPM: "Test Point, Multipurpose, Red, TH", Color=Red, Manufacturer=Keystone, Supplier Part Number 1=36-5010-ND
TVS1 TVS2 TVS3: "VARISTOR 430V 6KA DISC 14MM, EPCOS (TDK)", Manufacturer="EPCOS (TDK)", Supplier Part Number 1=495-1441-ND
U1 U2 U3: "SENSOR CURRENT HALL 100A AC/DC", Manufacturer="LEM USA Inc.", Supplier Part Number 1=398-1009-ND
U4 U6 U8 U9 U12 U13: "CONV DC/DC 2W 12VIN +20/-5VOUT T", Manufacturer="Recom Power", Supplier Part Number 1=945-3056-ND
U5 U7 U10 U11 U14 U15: "Isolated Gate Drivers with High CMTI and Scalable Drive Strength, D0008B (SOIC-8)", Alternate Manufacturer="Texas Instruments"
U16 U17 U18 U20 U24 U26 U28 U30: "General Purpose Amplifier 1 Circuit Rail-to-Rail SOT-23-5", Manufacturer="Microchip Technology", Supplier Part Number 1=MCP6021T-E/OTCT-ND, Total Supply Voltage(Max)(+5V is 5, +/-5V is 10)=5.5, Total Supply Voltage(Min)(+5V is 5, +/-5V is 10)=2.5
U19 U23 U25 U27 U29: "Precision +/-250-mV Input, 3-us Delay, Reinforced Isolated Amplifier, DWV0008A (SOIC-8)", Alternate Manufacturer="Texas Instruments", Alternate PartNumber=AMC1301DWV
U21: "IC VREF SERIES 1.65V/3.3V 5SOT"
U22 U31: "Miniature, 1 W, 3 kVDC Isolated DC-DC Converter, -40 to 85 degC, 4-pin Module (EDJ4), Pb-Free (RoHS)", Alternate Manufacturer="Texas Instruments", Alternate PartNumber=Equivalent, Supplier Part Number 1=296-20638-ND
U34: "Linear Voltage Regulator IC  1 Output  1A SOT-223", Manufacturer="Microchip Technology"
U35: library part S24SE12002NDFA, "DC/DC CONVERTER 12V 1.67A 6DIP", Manufacturer="Delta Electronics", Supplier Part Number 1=941-1628-ND
U36: "2.25 A, 4.5 to 18 V Input Wide Adjust Miniature Power Module, -40 to 85 degC, 5-pin Module (EUF5), Pb-Free (RoHS)", Alternate Manufacturer="Texas Instruments", Alternate PartNumber=Equivalent, Supplier Part Number 1=296-20432-ND
U37: "DC/DC CONVERT +/-15V 330MA 6DIP", Manufacturer="Delta Electronics", Supplier Part Number 1=941-1626-ND
U38: "CAN Interface IC Industrial Grade CAN TRX with VIO PIN (SO8)", Manufacturer="Microchip Technology / Atmel", PACKAGE_DESIGNATOR=D
U39 U40 U41: library part MCP6V51T-E/OT, "SINGLE, 45V ZERO-DRIFT OP AMP, E", Alternate Manufacturer="Microchip Technology"
U42: "IC VREF SERIES 3.3V SOT23-3", Manufacturer="Texas Instruments", Supplier Part Number 1=296-26324-2-ND
U43: "BRUSHED MOTOR DRIVER IC 2-CHANNE", Alternate Manufacturer="Toshiba Semiconductor and Storage"
W1 W2 W3 W4 W5 W6 W7 W8 W9 W10 W11 W12 W13 W14 W15 W16: library part "WASHER SHOULDER - 3065", "WASHER SHOULDER #8 FIBRE"
XF1: "6*5591-52-R, 3*50C14X51AM"
XF2: "GDT 470V 20KA THROUGH HOLE,  Littelfuse Inc.", Manufacturer="Littelfuse Inc.", Supplier Part Number 1=F2739-ND

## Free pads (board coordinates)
  round 1.524 hole 0.762: 0(334.772,163.322)

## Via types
v1: diameter 1.27, hole 0.711, Top Layer to Bottom Layer, 487 vias
v2: diameter 0.889, hole 0.508, Top Layer to Bottom Layer, 425 vias
v3: diameter 0.762, hole 0.457, Top Layer to Bottom Layer, 28 vias
v4: diameter 0.889/0.889/0.889/0.889/0.889/0.889 (per signal layer), hole 0.508, Top Layer to Bottom Layer, 1 vias

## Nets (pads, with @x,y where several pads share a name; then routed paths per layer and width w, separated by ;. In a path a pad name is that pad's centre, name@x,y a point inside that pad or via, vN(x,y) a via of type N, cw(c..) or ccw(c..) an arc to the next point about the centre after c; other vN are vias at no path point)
5V_M: C154.2 C163.2 C172.1 C173.1 L7.2 U27.1 U29.1 | length 24.8
  Signal Layer 1 w1.5: 249.682,47.752 250.19,47.244 v2(250.19,23.114)
  other v2: 251.46,18.542 249.174,32.004 250.444,32.004 249.174,47.752 250.19,47.752
5V_N: C116.2 C131.2 C136.1 C137.1 C144.2 L5.2 U19.1 U23.1 U25.1 | length 2.4
  Bottom Layer w0.508: C116.2@88.646,104.902 U19.1@91.048,104.902
  other v1: 67.056,104.902 90.17,104.902 113.284,104.902 132.334,105.156 133.35,105.156
12V_IN: C232.1 C233.1 C234.1 C235.1 C236.1 C237.1 J6.1 J7.2 J8.2 J9.2 R163.2 S1.2 | length 206.6
  Top Layer w0.508: J6.1@244.046,13.462 R163.2@248.412,13.462
  Top Layer w2: S1.2@229.87,9.398 229.87,11.938
  Top Layer w3: 229.87,11.938 231.6,13.668 J6.1@242.062,13.668 J6.1@243.84,13.668
  Bottom Layer w1.016: J9.2@292.178,53.672 J9.2@292.354,53.848
  Bottom Layer w1.524: 289.13,60.96 296.636,60.96 cw(c296.636,58.42) 298.432,60.216 304.31,54.338 ccw(c306.106,56.134) 306.106,53.594 310.642,53.594 352.262,53.594 ccw(c352.262,56.134) 354.058,54.338 355.507,55.787 cw(c357.303,53.991) 357.303,56.531 361.95,56.531 cw(c361.95,53.991) 364.49,53.991 J8.2@364.49,53.848 ; C234.1@363.806,56.134 C235.1@363.806,58.674
  Bottom Layer w2: S1.2@229.87,8.89 229.87,11.938 231.6,13.668 J6.1@242.062,13.668 255.222,13.668 260.096,18.542 260.096,46.228 266.446,52.578 ; C237.1@266.27,58.166 266.27,59.514 267.716,60.96 289.13,60.96 C233.1@291.924,58.166
+3.3V: C34.1 C35.1 C109.1 C111.1 C113.1 C117.2 C118.2 C119.1 C132.2 C133.2 C134.1 C145.2 C146.2 C147.1 C155.2 C156.2 C157.1 C164.2 C165.2 C166.1 C198.1 C216.1 C217.1 C256.1 C257.1 J12.4 L1.1 L10.1 R2.2 R166.2 U16.5 U17.5 U18.5 U19.8 U20.5 U23.8 U24.5 U25.8 U26.5 U27.8 U28.5 U29.8 U30.5 U34.3 U38.5 | length 57.5
  Top Layer w0.508: C109.1@131.572,175.768 131.638,175.834 U16.5@133.499,175.834 U16.5@133.753,175.834 ; C111.1@143.637,175.846 143.703,175.912 U18.5@145.564,175.912 U18.5@145.818,175.912 ; C113.1@155.448,175.641 U17.5@157.48,175.641 U17.5@157.734,175.641 ; R2.2@162.306,89.662 v2(162.306,90.932) ; C166.1@226.39,49.632 228.637,49.632 U30.5@228.742,49.737 ; C157.1@226.416,33.784 228.663,33.784 U28.5@228.768,33.889 ; C155.2@236.322,29.335 238.354,29.335 C156.2@238.492,29.473 ; C164.2@236.423,45.187 238.582,45.187 238.212,45.557 U29.8@238.212,48.87 ; C156.2@238.238,29.473 U27.8@238.238,33.022
  Top Layer w1: v2(177.47,50.354) 177.532,50.292 R166.2@179.07,50.292 ; R166.2@179.008,50.354 R166.2@179.07,50.292 ; C216.1@179.07,44.704 R166.2@179.07,50.292
  Bottom Layer w0.508: C133.2@64.262,91.44 C132.2@64.262,93.853 64.273,93.864 U23.8@67.945,93.864 ; U24.5@73.384,83.886 73.853,83.886 C134.1@75.311,85.344 ; C117.2@87.63,91.44 C118.2@87.63,93.853 ; C118.2@87.641,93.864 U19.8@91.186,93.864 ; U20.5@96.752,83.886 97.094,83.886 C119.1@98.552,85.344 ; C145.2@110.617,91.44 C146.2@110.617,93.98 114.184,93.98 U25.8@114.3,93.864 ; U26.5@119.866,83.886 120.208,83.886 C147.1@121.666,85.344
  Bottom Layer w1.016: C118.2@87.63,93.853 C118.2@87.641,93.864
  other v2: 237.744,29.464 227.686,34.038 177.47,40.194 177.47,42.734 237.744,45.212 177.47,45.274 177.47,47.814 224.79,49.911 158.242,66.04 75.184,84.074 98.044,84.074 121.412,84.074 110.744,90.17 64.262,90.424 87.63,90.424 177.419,109.22 178.435,109.22 179.451,109.22 180.467,109.22 181.483,109.22 177.419,110.236 178.435,110.236 179.451,110.236 180.467,110.236 181.483,110.236 154.002,175.641 130.126,175.768 142.191,175.768 109.728,176.022 109.728,177.292
+3.3V_2: C258.1 C259.1 C260.1 C261.1 L10.2 U43.5 | length 21.6
  Top Layer w0.33: U43.5@81.056,181.06 81.056,182.323 81.359,182.626 84.074,182.626 C261.1@85.344,181.356
  Top Layer w0.762: C261.1@85.344,181.356 C261.1@85.598,181.356 85.598,179.07 88.392,176.276 97.282,176.276
+3.3V_D: C25.1 C26.1 C36.1 C37.1 C65.1 C66.1 C91.1 C92.1 L1.2 R17.2 R18.2 R34.2 R35.2 R50.2 R51.2 U5.1 U7.1 U10.1 U11.1 U14.1 U15.1 | length 28.7
  Top Layer w0.508: C25.1@174.752,151.511 174.752,148.706 175.757,147.701 U5.1@176.657,147.701 ; C26.1@175.006,184.785 175.006,182.234 175.006,182.372 U7.1@176.276,181.102 ; C65.1@256.745,150.749 256.745,147.944 257.75,146.939 U10.1@258.65,146.939 ; C66.1@256.921,185.293 256.921,182.742 258.18,181.483 U11.1@258.572,181.483 ; C92.1@339.09,184.658 339.09,181.864 340.233,180.721 U15.1@340.857,180.721 ; C91.1@339.344,150.876 339.344,149.261 ccw(c341.884,149.261) 340.088,147.465 U14.1@340.487,147.066
  other v2: 186.182,109.22 189.23,109.22 190.246,109.22 191.262,109.22 186.182,110.236 187.198,110.236 188.214,110.236 189.23,110.236 190.246,110.236 191.262,110.236 251.46,140.462 333.756,140.716 169.418,141.478 257.048,152.146 339.344,152.4 175.006,152.908 332.994,174.498 168.91,174.752 250.952,175.26 339.09,185.928 175.26,186.182 257.048,186.69
+5V: C135.1 C171.1 C214.1 C215.1 C218.1 C242.2 C252.1 J5.57 J5.59 L3.1 L4.1 L6.1 R165.2 U34.1 U36.3 U38.3 U42.1 | length 44
  Top Layer w0.508: C242.2@150.241,67.945 150.622,67.945 151.13,68.453 U38.3@152.781,68.453 ; U36.3@205.994,46.482 208.153,48.641 R165.2@208.788,48.641
  Top Layer w0.762: v2(150.876,81.788) J5.59@153.565,81.788 ; v2(150.876,83.058) J5.57@153.565,83.058
  Top Layer w1.016: C252.1@127.692,170.872 C252.1@127.762,170.942 ; v2(187.63,43.623) 187.63,46.406 191.77,50.546 202.043,50.546 v2(203.886,48.703) ; C171.1@233.401,20.295 L6.1@233.401,22.327
  Top Layer w1.35: 182.88,41.91 C218.1@187.96,41.91
  Top Layer w1.5: C252.1@127.692,170.872 U42.1@127.692,172.786
  Top Layer w2: 127.762,169.418 C252.1@127.762,170.942
  other v2: 234.95,20.32 234.95,22.098 188.976,43.561 185.09,43.623 186.36,43.623 188.976,44.831 185.09,44.893 186.36,44.893 187.63,44.893 203.773,45.644 203.773,46.66 203.773,47.676 204.902,48.703 205.918,48.703 206.934,48.703 131.064,63.5 148.844,68.072 134.366,89.662 135.382,89.662 127.254,169.164 128.348,169.164
+12V: C51.1 C52.1 C190.1 C191.1 C209.1 C210.1 C223.1 C224.1 C225.1 C240.1 C241.1 L2.1 L8.1 L9.1 R164.2 U35.6 U37.1 | length 32.8
  Top Layer w1.016: R164.2@199.136,30.988 200.152,30.988 ; 202.248,30.416 U35.6@205.994,26.67
  Top Layer w2.5: 207.518,21.844 211.426,17.936 C241.1@214.63,17.936 C240.1@221.742,17.936
  Bottom Layer w2: L8.1@103.886,176.53 C191.1@107.696,176.53
  Bottom Layer w2.5: 207.772,31.75 212.598,36.576
  other v1: 200.66,20.32 202.184,20.32 203.708,20.32 205.232,20.32 206.756,20.32 200.66,21.971 202.184,21.971 203.708,21.971 205.232,21.971 206.756,21.971 200.66,23.622 202.184,23.622 203.708,23.622 205.232,23.622 206.756,23.622 200.66,25.273 202.184,25.273 200.66,26.924 202.184,26.924 200.914,28.956 202.438,28.956 203.962,28.956 205.486,28.956 207.01,28.956 102.108,182.88 104.14,182.88 102.108,184.658 104.14,184.658 102.108,186.436 104.14,186.436
  other v2: 177.546,100.584 178.562,100.584 179.578,100.584 180.594,100.584 181.61,100.584 182.626,100.584 177.546,101.6 178.562,101.6 179.578,101.6 180.594,101.6 181.61,101.6 182.626,101.6
+12V_D: C29.1 C30.1 C38.1 C39.1 C53.1 C54.1 C55.1 C56.1 C63.1 C64.1 C71.1 C72.1 C89.1 C90.1 C97.1 C98.1 L2.2 U4.1 U6.1 U8.1 U9.1 U12.1 U13.1 | length 173.2
  Signal Layer 1 w2.5: 191.643,101.219 199.009,101.219 201.93,104.14 339.09,104.14 350.126,115.176 U12.1@350.126,119.233
  Bottom Layer w1.016: U12.1@350.258,119.38 C89.1@352.806,119.38 C90.1@355.092,119.38
  other v2: 184.658,100.584 185.674,100.584 186.69,100.584 187.706,100.584 188.722,100.584 189.738,100.584 184.658,101.6 185.674,101.6 186.69,101.6 187.706,101.6 188.722,101.6 189.738,101.6 253.746,107.188 255.016,107.188 256.286,107.188 253.746,108.458 255.016,108.458 256.286,108.458 333.871,108.597 335.141,108.597 336.411,108.597 255.016,109.728 256.286,109.728 333.871,109.867 335.141,109.867 336.411,109.867 333.871,111.137 335.141,111.137 336.411,111.137
  other v4: 253.746,109.728
+12V_D2: C192.1 C193.1 C194.1 C195.1 C196.1 C197.1 C262.1 L8.2 U43.9 | length 31.6
  Top Layer w2: 83.836,188.468 C262.1@85.598,188.468 C262.1@86.106,188.468 ; v3(86.995,187.579) C262.1@86.106,188.468 ; v3(86.995,188.468) C262.1@86.106,188.468
  Bottom Layer w2: C197.1@87.63,176.276 C197.1@87.63,176.53 ; L8.2@100.838,176.53 C197.1@87.63,176.53 ; 87.341,187.36 87.341,177.513 87.63,177.224 C197.1@87.63,176.53 ; 87.341,187.36 86.995,187.706 86.995,187.833 86.868,187.833 86.741,187.96 86.741,188.468 87.341,187.868 87.341,187.36
  other v3: 86.995,186.69 86.995,189.357
+15V: C2.1 C3.1 C4.1 C5.1 C6.1 C7.1 C219.1 C221.1 C222.1 C243.1 C246.1 C249.1 R169.2 U1.8 U2.8 U3.8 U37.6 U39.5 U40.5 U41.5 | length 121.9
  Top Layer w0.508: C243.1@131.638,187.518 U39.5@133.753,187.518 ; C246.1@155.448,187.579 C246.1@155.514,187.645
  Top Layer w0.762: U1.8@129.921,199.746 128.524,198.349 128.524,189.865 130.937,187.452 U39.5@133.985,187.452 ; U41.5@145.713,187.264 142.428,187.264 141.605,188.087 141.605,197.485 143.764,199.644 U3.8@148.463,199.644 ; U3.8@149.225,199.746 151.409,199.746 153.619,197.536 153.619,188.392 154.432,187.579 C246.1@155.448,187.579 ; C246.1@155.514,187.645 U40.5@157.629,187.645
  Top Layer w1: R169.2@103.632,205.486 105.664,205.486 107.696,203.454 v2(107.696,203.327)
  Bottom Layer w2: U37.6@110.49,201.168 111.912,199.746 U1.8@130.683,199.746 ; U1.8@130.937,199.746 U3.8@148.971,199.746 ; U3.8@149.225,199.746 U2.8@167.767,199.746
+20V1: C31.1 C32.1 C47.1 C48.1 U6.7 U7.5 | length 4.8
  Top Layer w0.508: C48.1@184.912,175.387 C47.1@187.452,175.387
  Top Layer w0.8: U7.5@182.137,177.165 184.404,177.165
  other v1: 189.23,175.006 189.23,176.022
+20V2: C27.1 C28.1 C45.1 C46.1 U4.7 U5.5 | length 17.4
  Top Layer w0.508: 184.774,144.018 184.774,142.251 C46.1@184.912,142.113 C45.1@187.452,142.113
  Top Layer w0.8: U5.5@182.137,143.891 184.585,143.891
  Top Layer w2: U4.7@186.804,134.996 187.828,134.996 190.5,137.668 190.5,140.462 188.468,142.494
+20V3: C69.1 C70.1 C79.1 C80.1 U9.7 U11.5 | length 7.1
  Top Layer w0.508: 266.689,177.8 266.689,176.033 C80.1@266.827,175.895 C79.1@269.367,175.895
  Top Layer w0.8: U11.5@264.052,177.673 266.629,177.673
  other v1: 271.018,175.768 271.018,176.784
+20V4: C59.1 C60.1 C77.1 C78.1 U8.7 U10.5 | length 17.9
  Top Layer w0.508: 266.596,143.129 266.767,142.958 ; 266.767,143.256 266.767,142.958 ; C77.1@269.445,141.351 C78.1@266.905,141.351 266.767,141.489 266.767,142.958
  Top Layer w0.8: U10.5@264.13,143.129 266.596,143.129
  Top Layer w2: U8.7@268.084,134.996 270.124,134.996 272.288,137.16 272.288,139.954 270.51,141.732 270.256,141.732
+20V5: C95.1 C96.1 C105.1 C106.1 U13.7 U15.5 | length 6.9
  Top Layer w0.508: 348.974,177.038 348.974,175.409 C106.1@349.123,175.26 C105.1@351.663,175.26
  Top Layer w0.8: U15.5@346.337,176.911 348.872,176.911
  other v1: 353.314,175.006 353.314,176.022
+20V6: C85.1 C86.1 C103.1 C104.1 U12.7 U14.5 | length 18.7
  Top Layer w0.508: C104.1@348.604,141.616 C104.1@348.742,141.478 C103.1@351.282,141.478
  Top Layer w0.8: U14.5@345.967,143.256 348.869,143.256 349.758,142.367
  Top Layer w2: U12.7@350.126,134.488 352.166,134.488 354.33,136.652 354.33,140.208 352.806,141.732 C103.1@351.79,141.732
-5V1: C23.1 C24.1 C43.2 C44.2 R6.2 U6.5 | length 12.6
  Top Layer w2: 188.468,185.42 188.468,193.802 190.378,195.712 U6.5@191.91,195.712
-5V2: C21.1 C22.1 C41.2 C42.2 R5.2 U4.5
  other v2: 188.976,151.638 188.976,152.908 188.976,154.178 188.976,155.448 188.976,156.718
-5V3: C61.1 C62.1 C75.2 C76.2 R23.2 U9.5 | length 11.9
  Top Layer w2: 270.256,186.182 270.256,194.31 272.166,196.22 U9.5@273.19,196.22
-5V4: C57.1 C58.1 C67.2 C68.2 R22.2 U8.5
  other v2: 270.51,151.409 270.51,152.679 270.51,153.949 270.51,155.219 270.51,156.489
-5V5: C87.1 C88.1 C101.2 C102.2 R39.2 U13.5 | length 12.3
  Top Layer w2: 352.552,185.42 352.552,193.548 354.208,195.204 U13.5@355.994,195.204
-5V6: C83.1 C84.1 C93.2 C94.2 R38.2 U12.5
  other v2: 352.806,151.384 352.806,152.654 352.806,153.924 352.806,155.194 352.806,156.464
